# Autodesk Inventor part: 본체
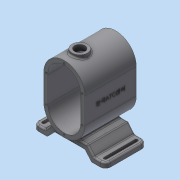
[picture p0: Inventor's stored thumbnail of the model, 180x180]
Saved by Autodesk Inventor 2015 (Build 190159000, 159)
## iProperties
Created: 2016-12
Part Number: 본체
Material: 알루미늄 6061
Document SubType Name: Modeling
Designer: mduedu
Density: 2.71 g/cm^3
Appearance: 기본값
Mass: 1017.22 g
Surface Area: 965.791 cm^2
Volume: 375.358 cm^3
Author: mduedu
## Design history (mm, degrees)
sketch "스케치1"
  geometry: L1 (40, -25)-(40, 25); L2 (-40, 25)-(-40, -25); L3 (-40, -25)-(40, 25); L4 (40, -25)-(-40, 25); L5 (0, 25)-(0, -25); A1 r 40 centre (0, 25) between (40, 25) and (-40, 25); A2 r 40 centre (0, -25) between (-40, -25) and (40, -25); 1 further point
  constraints: 10 end point, 4 point on circle, 3 tangent, 2 centre point, 2 midpoint, 2 parallel, 1 vertical
  dimensions: "d0" = 130 dimension on A2 A1; "d2" = 80 distance between parallel lines of L1 L2
extrude "돌출1" new body sketch "스케치1" stored distance "d3" = 100; taper "d4" = 0 deg
feature "쉘1" dims "d5" = 8
sketch "스케치15"
  geometry: L1 (-35, -64.5)-(35, -64.5); L2 (-35, -64.5)-(-47.586, -79.5); L3 (-47.586, -79.5)-(-70, -79.5); L4 (0, -64.5)-(0, 0); L5 (35, -64.5)-(47.586, -79.5); L6 (47.586, -79.5)-(70, -79.5); L7 (70, -89.5)-(42.923, -89.5); L8 (42.923, -89.5)-(30.337, -74.5); L9 (30.337, -74.5)-(-30.337, -74.5); L10 (-30.337, -74.5)-(-42.923, -89.5); L11 (-42.923, -89.5)-(-70, -89.5); L12 (-70, -79.5)-(-70, -89.5); L13 (70, -79.5)-(70, -89.5); A1 r 40 centre (0, -25) between (-40, -25) and (40, -25) reference; 1 further point
  constraints: 26 end point, 2 parallel, 2 perpendicular, 2 symmetric about line, 1 coincident, 1 horizontal, 1 midpoint, 1 vertical, 4 other
  dimensions: "d83" = 10 distance between parallel lines of L9 L1; "d85" = 140 distance between parallel lines of L13 L12; "d86" = 70 distance of L1.start L1.end; "d87" = 25 distance between parallel lines of L11 L1; "d88" = 130 deg angle of L1 L2; "d106" = 0.5 distance edge to line of A1 L1
extrude "돌출6" new body sketch "스케치15" stored distance "d89" = 80; taper "d90" = 0 deg
fillet "모깎기13" dims "d101" = 3
fillet "모깎기15" dims "d103" = 3
fillet "모깎기16" dims "d104" = 10
fillet "모깎기17" dims "d105" = 3
feature "결합2"
  node "솔리드2"
fillet "모깎기18" dims "d107" = 3
sketch "스케치16"
  geometry: L1 (8.015, 67)-(8.015, 7); L2 (14.015, 67)-(14.015, 7); A1 r 10 centre (11.015, 67) between (21.015, 67) and (11.015, 77) reference; A2 r 10 centre (11.015, 7) between (11.015, -3) and (21.015, 7) reference; A3 r 3 centre (11.015, 67) between (8.015, 67) and (14.015, 67); A4 r 3 centre (11.015, 7) between (8.015, 7) and (14.015, 7); 1 further point
  constraints: 4 end point, 4 point on circle, 4 tangent, 2 centre point, 2 coincident
  dimensions: "d108" = 6 diameter of A3; "d109" = 6 diameter of A4
extrude "돌출7" cut sketch "스케치16" stored distance "d110" = 80; taper "d111" = 0 deg
node "작업 평면1"
sketch "스케치9"
  geometry: 1 further point
sketch "스케치7"
  geometry: L1 (40, 50)-(-40, 50) reference; C1 r 15 at (0, 20); 1 further point
  constraints: 1 centre point, 1 vertical alignment
  dimensions: "d40" = 30 diameter of C1; "d41" = 30 distance from line of C1.centre L1
extrude "돌출4" join sketch "스케치7" stored distance "d42" = 80; taper "d43" = 0 deg
hole "구멍2" diameter "d46" = 20; stored, may be unused: countersink angle "d50" = 90 deg, drill point angle "d52" = 118 deg; dims "d44" = 10, "d45" = 10, "d47" = 6, "d48" = 4, "d49" = 2, "d51" = 8
fillet "모깎기4" dims "d53" = 3
node "작업 평면2"
sketch "스케치8"
  geometry: C1 r 15 at (0, 0) reference; C2 r 15 at (0, 0); 1 further point
  constraints: 1 centre point, 1 coincident
  dimensions: "d55" = 30 diameter of C2
extrude "돌출5" cut sketch "스케치8" stored distance "d56" = 80; taper "d57" = 0 deg
chamfer "모따기1" distance "d58" = 1; stored, may be unused: second distance "d59" = 2, angle "d60" = 45 deg
sketch "스케치10"
  geometry: 2 further points
  constraints: 1 coincident, 1 other
feature "엠보싱1" sketch "스케치10" dims "d0" = 130, "d2" = 80, "d61" = 0.5, "d62" = 0
sketch "스케치11"
  geometry: 1 further point
  constraints: 1 other
hole "구멍3" sketch "스케치11" at (0, 60) diameter "d63" = 3.242; stored, may be unused: countersink angle "d67" = 90 deg, drill point angle "d69" = 120 deg; dims "d64" = 8.6, "d65" = 4, "d66" = 2, "d68" = 10.6
sketch "스케치12"
  geometry: 1 further point
  constraints: 1 other
hole "구멍5" sketch "스케치12" at (0, 60) diameter "d70" = 3.242; stored, may be unused: countersink angle "d74" = 90 deg, drill point angle "d76" = 120 deg; dims "d71" = 8.6, "d72" = 4, "d73" = 2, "d75" = 10.6
node "솔리드1"
mirror "대칭2"
pattern_linear "직사각형 패턴1"
pattern_linear "직사각형 패턴2"
sketch "스케치13"
  geometry: L1 (-40, 25)-(-40, -25) reference; L2 (40, -25)-(40, 25) reference; L3 (35, 25)-(35, -25); L4 (-35, -25)-(-35, 25); A1 r 40 centre (0, 25) between (40, 25) and (-40, 25) reference; A2 r 40 centre (0, -25) between (-40, -25) and (40, -25) reference; A3 r 35 centre (0, 25) between (35, 25) and (-35, 25); A4 r 35 centre (0, -25) between (-35, -25) and (35, -25); 2 further points
  constraints: 5 point on circle, 4 end point, 2 centre point, 3 other
  dimensions: "d77" = 5 distance between parallel lines of L3 L2
sketch "스케치14"
  geometry: L1 (-40, 25)-(-40, -25) reference; L2 (40, -25)-(40, 25) reference; L3 (35, 25)-(35, -25); L4 (-35, -25)-(-35, 25); A1 r 40 centre (0, 25) between (40, 25) and (-40, 25) reference; A2 r 40 centre (0, -25) between (-40, -25) and (40, -25) reference; A3 r 35 centre (0, 25) between (35, 25) and (-35, 25); A4 r 35 centre (0, -25) between (-35, -25) and (35, -25); 2 further points
  constraints: 5 point on circle, 4 end point, 2 centre point, 3 other
  dimensions: "d80" = 5 distance between parallel lines of L2 L3
other parameters: "d54" = -8
